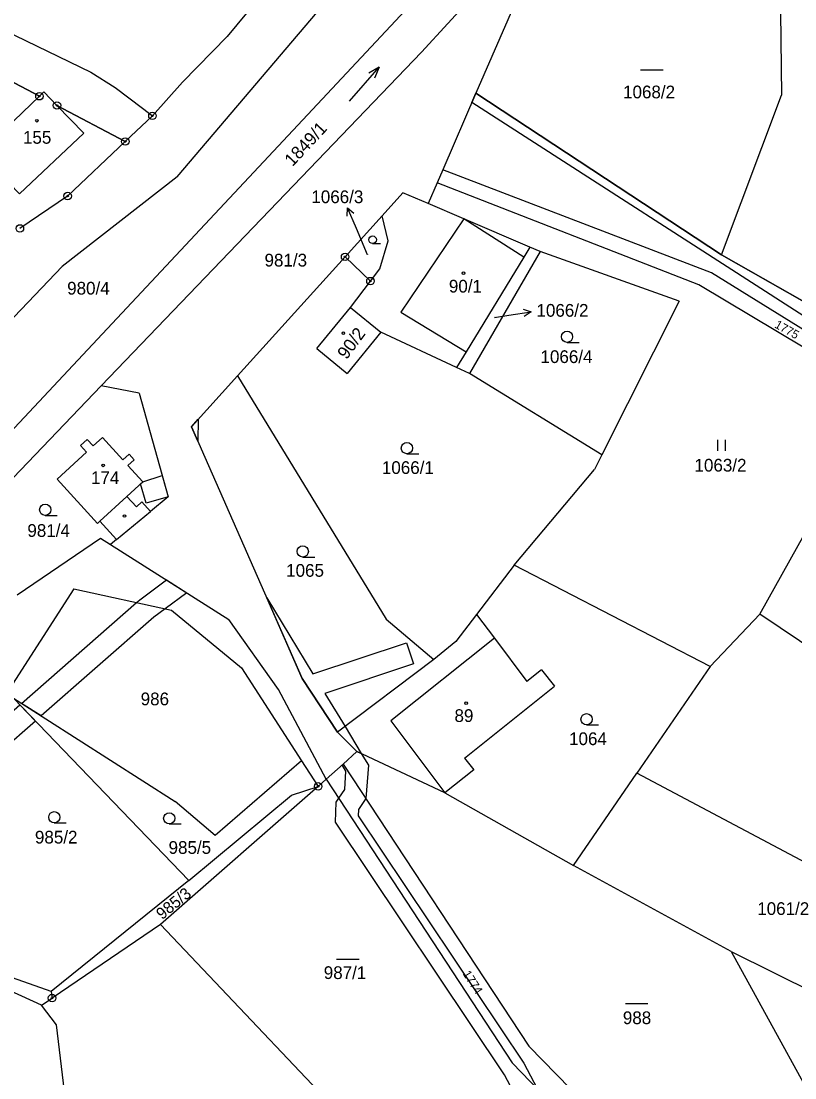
# Model space of a CAD drawing. Extents: x -546762 to -540209, y -1046851 to -1035694.
# Drawn here: x -543695 to -543591.5, y -1041824.4 to -1041683.1 of the extents above; entities that cross this region are included whole.
import ezdxf

# ---------------------------------------------------------------- set-up
doc = ezdxf.new("R2010")
doc.units = 0
for name, color, linetype in [('Vrstva 1', 7, 'Continuous'), ('Vrstva 16', 7, 'Continuous'), ('Vrstva 18', 7, 'Continuous'), ('Vrstva 19', 7, 'Continuous'), ('Vrstva 24', 7, 'Continuous'), ('Vrstva 25', 7, 'Continuous'), ('Vrstva 3', 7, 'Continuous'), ('Vrstva 30', 7, 'Continuous'), ('Vrstva 37', 7, 'Continuous'), ('Vrstva 4', 7, 'Continuous')]:
    doc.layers.add(name, color=color, linetype=linetype)

msp = doc.modelspace()

# ---------------------------------------------------------------- linework, layer by layer
at = {"layer": 'Vrstva 1'}
for p, q in [((-543658.84, -1041786.63), (-543655.29, -1041785.44)), ((-543672.56, -1041798.03), (-543658.84, -1041786.63)), ((-543672.56, -1041798.03), (-543690.99, -1041812.85)), ((-543676.36, -1041803.9), (-543690.87, -1041813.74)), ((-543690.99, -1041812.85), (-543690.87, -1041813.74)), ((-543692.27, -1041814.69), (-543690.87, -1041813.74))]:
    msp.add_line(p, q, dxfattribs=at)
for points in [[(-543593.64, -1041667.16), (-543593.33, -1041693.04)], [(-543641.49, -1041687.28), (-543627.37, -1041671.93)], [(-543658.62, -1041674.52), (-543667.47, -1041685.2), (-543673.41, -1041691.3), (-543677.45, -1041695.81)], [(-543674.15, -1041703.97), (-543649.79, -1041675.31)], [(-543626.72, -1041675.58), (-543634.2, -1041692.8)], [(-543720.78, -1041764.01), (-543643, -1041681.02)], [(-543706.63, -1041685.77), (-543692.56, -1041693.19)], [(-543641.49, -1041687.28), (-543684.31, -1041731.91)], [(-543692.56, -1041693.19), (-543691.96, -1041692.62), (-543690.21, -1041694.42)], [(-543634.2, -1041692.8), (-543638.64, -1041703.04)], [(-543601.37, -1041714.39), (-543634.2, -1041692.8)], [(-543601.37, -1041714.39), (-543593.33, -1041693.04)], [(-543690.21, -1041694.42), (-543686.63, -1041698.12), (-543695.23, -1041706.25), (-543700.53, -1041700.78), (-543692.56, -1041693.19)], [(-543690.21, -1041694.42), (-543681.08, -1041699.24)], [(-543681.08, -1041699.24), (-543677.45, -1041695.81)], [(-543681.08, -1041699.24), (-543688.79, -1041706.53), (-543695.17, -1041710.86)], [(-543674.15, -1041703.97), (-543689.53, -1041715.93)], [(-543638.64, -1041703.04), (-543639.38, -1041704.75)], [(-543602.7, -1041716.81), (-543638.64, -1041703.04)], [(-543639.38, -1041704.75), (-543640.6, -1041707.54)], [(-543604.41, -1041718.39), (-543639.38, -1041704.75)], [(-543646.74, -1041709.16), (-543643.97, -1041706.1)], [(-543640.6, -1041707.54), (-543643.97, -1041706.1)], [(-543635.79, -1041709.59), (-543640.6, -1041707.54)], [(-543646.74, -1041709.16), (-543651.69, -1041714.65)], [(-543645.91, -1041712.53), (-543646.74, -1041709.16)], [(-543626.97, -1041713.36), (-543635.79, -1041709.59)], [(-543647.06, -1041716.27), (-543645.91, -1041712.53)], [(-543625.6, -1041713.94), (-543635.04, -1041730.25)], [(-543626.97, -1041713.36), (-543627.8, -1041714.72)], [(-543625.6, -1041713.94), (-543626.97, -1041713.36)], [(-543607.02, -1041720.58), (-543625.6, -1041713.94)], [(-543651.69, -1041714.65), (-543666.07, -1041730.55)], [(-543651.69, -1041714.65), (-543648.3, -1041717.9)], [(-543627.8, -1041714.72), (-543635.51, -1041727.36)], [(-543579.06, -1041727.05), (-543601.37, -1041714.39)], [(-543689.53, -1041715.93), (-543716.11, -1041743.8)], [(-543648.3, -1041717.9), (-543647.06, -1041716.27)], [(-543579.17, -1041731.38), (-543602.7, -1041716.81)], [(-543650.98, -1041721.41), (-543648.3, -1041717.9)], [(-543583.37, -1041730.98), (-543604.41, -1041718.39)], [(-543607.02, -1041720.58), (-543617.34, -1041741.14)], [(-543655.46, -1041726.92), (-543650.98, -1041721.41)], [(-543650.98, -1041721.41), (-543646.91, -1041724.72)], [(-543646.91, -1041724.72), (-543651.39, -1041730.23)], [(-543636.78, -1041729.44), (-543646.91, -1041724.72)], [(-543655.46, -1041726.92), (-543651.39, -1041730.23)], [(-543635.51, -1041727.36), (-543636.78, -1041729.44)], [(-543635.04, -1041730.25), (-543636.78, -1041729.44)], [(-543666.07, -1041730.55), (-543672.23, -1041737.37)], [(-543666.07, -1041730.55), (-543646.18, -1041763.1)], [(-543617.34, -1041741.14), (-543635.04, -1041730.25)], [(-543684.31, -1041731.91), (-543698.08, -1041746.26)], [(-543679.24, -1041732.88), (-543684.31, -1041731.91)], [(-543679.24, -1041732.88), (-543675.36, -1041746.73)], [(-543596.22, -1041762.41), (-543580.22, -1041733.75)], [(-543672.23, -1041737.37), (-543657.42, -1041771.01)], [(-543686.19, -1041739.06), (-543687.08, -1041739.87)], [(-543686.19, -1041739.06), (-543685.38, -1041739.94)], [(-543684.13, -1041738.79), (-543685.38, -1041739.94)], [(-543681.39, -1041741.79), (-543684.13, -1041738.79)], [(-543686.27, -1041740.75), (-543690.19, -1041744.36)], [(-543687.08, -1041739.87), (-543686.27, -1041740.75)], [(-543680.58, -1041741.05), (-543681.39, -1041741.79)], [(-543679.9, -1041741.79), (-543680.58, -1041741.05)], [(-543680.72, -1041742.53), (-543679.9, -1041741.79)], [(-543617.34, -1041741.14), (-543618.32, -1041743.09)], [(-543678.73, -1041744.71), (-543680.72, -1041742.53)], [(-543629.09, -1041755.89), (-543618.32, -1041743.09)], [(-543690.19, -1041744.36), (-543684.79, -1041750.28)], [(-543680.89, -1041746.69), (-543678.73, -1041744.71)], [(-543680.89, -1041746.69), (-543679.6, -1041748.09)], [(-543675.36, -1041746.73), (-543677.7, -1041748.68)], [(-543678.87, -1041747.42), (-543679.6, -1041748.09)], [(-543677.7, -1041748.68), (-543678.87, -1041747.42)], [(-543682.24, -1041752.46), (-543677.7, -1041748.68)], [(-543684.79, -1041750.28), (-543684.5, -1041750.01)], [(-543684.5, -1041750.01), (-543682.24, -1041752.46)], [(-543695.54, -1041759.82), (-543684.39, -1041752.27)], [(-543684.39, -1041752.27), (-543683.04, -1041753.12)], [(-543682.24, -1041752.46), (-543683.04, -1041753.12)], [(-543683.04, -1041753.12), (-543667.22, -1041763.13)], [(-543629.09, -1041755.89), (-543634.11, -1041762.45)], [(-543602.89, -1041769.4), (-543629.09, -1041755.89)], [(-543687.98, -1041759.05), (-543696.98, -1041773.04)], [(-543687.98, -1041759.05), (-543674.92, -1041761.88)], [(-543674.92, -1041761.88), (-543665.56, -1041769.59)], [(-543660.58, -1041772.47), (-543667.22, -1041763.13)], [(-543646.18, -1041763.1), (-543639.82, -1041768.48)], [(-543634.11, -1041762.45), (-543636.89, -1041766.08)], [(-543634.11, -1041762.45), (-543631.72, -1041765.63)], [(-543602.89, -1041769.4), (-543596.22, -1041762.41)], [(-543577.6, -1041774.95), (-543596.22, -1041762.41)], [(-543636.89, -1041766.08), (-543639.82, -1041768.48)], [(-543631.72, -1041765.63), (-543627.37, -1041771.43)], [(-543639.82, -1041768.48), (-543652.71, -1041778.21)], [(-543665.56, -1041769.59), (-543657.51, -1041782.01)], [(-543625.42, -1041769.87), (-543627.37, -1041771.43)], [(-543625.42, -1041769.87), (-543623.67, -1041772.06)], [(-543602.89, -1041769.4), (-543612.68, -1041783.66)], [(-543657.42, -1041771.01), (-543652.71, -1041778.21)], [(-543635.71, -1041781.67), (-543623.67, -1041772.06)], [(-543654.2, -1041784.48), (-543660.58, -1041772.47)], [(-543696.04, -1041773.64), (-543674.43, -1041787.46)], [(-543696.04, -1041773.64), (-543672.56, -1041798.03)], [(-543652.71, -1041778.21), (-543650.11, -1041780.77)], [(-543657.51, -1041782.01), (-543669.07, -1041792.02)], [(-543657.51, -1041782.01), (-543655.29, -1041785.44)], [(-543650.11, -1041780.77), (-543651.96, -1041782.45)], [(-543638.36, -1041786.3), (-543650.11, -1041780.77)], [(-543635.71, -1041781.67), (-543634.47, -1041783.24)], [(-543651.96, -1041782.45), (-543654.2, -1041784.48)], [(-543651.96, -1041782.45), (-543627.14, -1041820.18)], [(-543634.47, -1041783.24), (-543638.36, -1041786.3)], [(-543654.2, -1041784.48), (-543655.29, -1041785.44)], [(-543654.2, -1041784.48), (-543629.36, -1041822.39)], [(-543621.17, -1041796.03), (-543612.68, -1041783.66)], [(-543555.05, -1041814.24), (-543612.68, -1041783.66)], [(-543655.29, -1041785.44), (-543676.36, -1041803.9)], [(-543638.36, -1041786.3), (-543621.17, -1041796.03)], [(-543669.07, -1041792.02), (-543674.43, -1041787.46)], [(-543600.05, -1041807.52), (-543621.17, -1041796.03)], [(-543646.37, -1041835.52), (-543676.36, -1041803.9)], [(-543690.99, -1041812.85), (-543714.27, -1041804.68)], [(-543692.27, -1041814.69), (-543714.27, -1041804.68)], [(-543600.05, -1041807.52), (-543560.44, -1041827.16)], [(-543600.05, -1041807.52), (-543584.78, -1041835.32)], [(-543690.28, -1041817.33), (-543692.27, -1041814.69)], [(-543686.39, -1041849.61), (-543690.28, -1041817.33)], [(-543627.14, -1041820.18), (-543614.13, -1041833.46)], [(-543629.36, -1041822.39), (-543624.43, -1041827.46)]]:
    msp.add_lwpolyline(points, dxfattribs=at)
at = {"layer": 'Vrstva 16'}
for p, q in [((-543650.18, -1041710.86), (-543651.36, -1041708.1)), ((-543629.79, -1041722.46), (-543626.82, -1041722.01))]:
    msp.add_line(p, q, dxfattribs=at)
for points in [[(-543651.42, -1041709.22), (-543651.36, -1041708.1), (-543650.5, -1041708.82)], [(-543648.67, -1041714.41), (-543650.18, -1041710.86)], [(-543631.69, -1041722.75), (-543629.79, -1041722.46)], [(-543627.89, -1041721.67), (-543626.82, -1041722.01), (-543627.74, -1041722.65)]]:
    msp.add_lwpolyline(points, dxfattribs=at)
at = {"layer": 'Vrstva 24'}
for centre, radius in [((-543692.56, -1041693.19), 0.5), ((-543692.56, -1041693.19), 0.1), ((-543690.21, -1041694.42), 0.5), ((-543690.21, -1041694.42), 0.1), ((-543677.45, -1041695.81), 0.5), ((-543677.45, -1041695.81), 0.1), ((-543681.08, -1041699.24), 0.5), ((-543681.08, -1041699.24), 0.1), ((-543688.79, -1041706.53), 0.5), ((-543688.79, -1041706.53), 0.1), ((-543695.17, -1041710.86), 0.5), ((-543651.69, -1041714.65), 0.5), ((-543651.69, -1041714.65), 0.1), ((-543648.3, -1041717.9), 0.5), ((-543648.3, -1041717.9), 0.1), ((-543655.29, -1041785.44), 0.5), ((-543655.29, -1041785.44), 0.1), ((-543690.87, -1041813.74), 0.5), ((-543690.87, -1041813.74), 0.1)]:
    msp.add_circle(centre, radius, dxfattribs=at)
at = {"layer": 'Vrstva 25'}
for p, q in [((-543612.17, -1041689.68), (-543609.17, -1041689.68)), ((-543648.01, -1041712.87), (-543646.94, -1041712.87)), ((-543622.01, -1041726.09), (-543620.41, -1041726.09)), ((-543601.84, -1041740.6), (-543601.84, -1041739.1)), ((-543600.84, -1041740.6), (-543600.84, -1041739.1)), ((-543643.43, -1041740.98), (-543641.83, -1041740.98)), ((-543691.79, -1041749.21), (-543690.19, -1041749.21)), ((-543657.35, -1041754.78), (-543655.75, -1041754.78)), ((-543619.4, -1041777.22), (-543617.8, -1041777.22)), ((-543690.57, -1041790.32), (-543688.97, -1041790.32)), ((-543675.2, -1041790.46), (-543673.6, -1041790.46)), ((-543652.82, -1041808.55), (-543649.82, -1041808.55)), ((-543614.21, -1041814.46), (-543611.21, -1041814.46))]:
    msp.add_line(p, q, dxfattribs=at)
for points in [[(-543651.09, -1041693.83), (-543647.13, -1041689.31), (-543648.5, -1041690.11)], [(-543647.13, -1041689.31), (-543647.75, -1041690.77)]]:
    msp.add_lwpolyline(points, dxfattribs=at)
for centre, radius in [((-543692.89, -1041696.46), 0.175), ((-543648.01, -1041712.37), 0.503), ((-543635.86, -1041716.83), 0.175), ((-543651.92, -1041724.86), 0.175), ((-543622.01, -1041725.34), 0.75), ((-543643.43, -1041740.23), 0.75), ((-543684.03, -1041742.53), 0.175), ((-543691.79, -1041748.46), 0.75), ((-543681.19, -1041749.3), 0.175), ((-543657.35, -1041754.03), 0.75), ((-543635.5, -1041774.31), 0.175), ((-543619.4, -1041776.47), 0.75), ((-543690.57, -1041789.57), 0.75), ((-543675.2, -1041789.71), 0.75)]:
    msp.add_circle(centre, radius, dxfattribs=at)
at = {"layer": 'Vrstva 3'}
for points in [[(-543692.56, -1041693.19), (-543691.96, -1041692.62), (-543690.21, -1041694.42)], [(-543690.21, -1041694.42), (-543686.63, -1041698.12), (-543695.23, -1041706.25), (-543700.53, -1041700.78), (-543692.56, -1041693.19)], [(-543635.79, -1041709.59), (-543644.22, -1041722.05)], [(-543627.8, -1041714.72), (-543635.79, -1041709.59)], [(-543627.8, -1041714.72), (-543635.51, -1041727.36)], [(-543655.46, -1041726.92), (-543650.98, -1041721.41)], [(-543650.98, -1041721.41), (-543646.91, -1041724.72)], [(-543644.22, -1041722.05), (-543635.51, -1041727.36)], [(-543646.91, -1041724.72), (-543651.39, -1041730.23)], [(-543655.46, -1041726.92), (-543651.39, -1041730.23)], [(-543686.19, -1041739.06), (-543687.08, -1041739.87)], [(-543686.19, -1041739.06), (-543685.38, -1041739.94)], [(-543684.13, -1041738.79), (-543685.38, -1041739.94)], [(-543681.39, -1041741.79), (-543684.13, -1041738.79)], [(-543686.27, -1041740.75), (-543690.19, -1041744.36)], [(-543687.08, -1041739.87), (-543686.27, -1041740.75)], [(-543680.58, -1041741.05), (-543681.39, -1041741.79)], [(-543679.9, -1041741.79), (-543680.58, -1041741.05)], [(-543680.72, -1041742.53), (-543679.9, -1041741.79)], [(-543678.73, -1041744.71), (-543680.72, -1041742.53)], [(-543690.19, -1041744.36), (-543684.79, -1041750.28)], [(-543680.89, -1041746.69), (-543678.73, -1041744.71)], [(-543680.89, -1041746.69), (-543684.5, -1041750.01)], [(-543684.79, -1041750.28), (-543684.5, -1041750.01)], [(-543631.72, -1041765.63), (-543645.57, -1041776.69)], [(-543631.72, -1041765.63), (-543627.37, -1041771.43)], [(-543625.42, -1041769.87), (-543627.37, -1041771.43)], [(-543625.42, -1041769.87), (-543623.67, -1041772.06)], [(-543635.71, -1041781.67), (-543623.67, -1041772.06)], [(-543645.57, -1041776.69), (-543638.36, -1041786.3)], [(-543635.71, -1041781.67), (-543634.47, -1041783.24)], [(-543634.47, -1041783.24), (-543638.36, -1041786.3)]]:
    msp.add_lwpolyline(points, dxfattribs=at)
at = {"layer": 'Vrstva 30'}
for p, q in [((-543634.73, -1041694.01), (-543634.2, -1041692.8)), ((-543634.2, -1041692.8), (-543601.37, -1041714.39)), ((-543567.29, -1041737.46), (-543634.73, -1041694.01)), ((-543601.37, -1041714.39), (-543579.06, -1041727.05))]:
    msp.add_line(p, q, dxfattribs=at)
for points in [[(-543711.17, -1041684.4), (-543702.42, -1041684.93), (-543697.27, -1041684.36), (-543685.67, -1041689.96), (-543682.42, -1041692.02), (-543678.79, -1041694.79), (-543677.45, -1041695.81), (-543681.08, -1041699.24), (-543690.21, -1041694.42), (-543691.96, -1041692.62), (-543692.56, -1041693.19), (-543706.63, -1041685.77), (-543711.24, -1041685.68), (-543711.17, -1041684.4)], [(-543672.23, -1041737.37), (-543671.32, -1041736.36), (-543671.39, -1041739.29), (-543672.23, -1041737.37)], [(-543678.73, -1041744.71), (-543676.15, -1041743.9), (-543675.36, -1041746.73), (-543678.28, -1041747.57), (-543679.04, -1041745), (-543678.73, -1041744.71)], [(-543679.58, -1041760.87), (-543679.14, -1041760.49), (-543675.58, -1041757.84), (-543672.86, -1041759.56), (-543675.74, -1041761.7), (-543677.26, -1041762.83), (-543692.31, -1041776.02), (-543694.94, -1041774.34), (-543679.58, -1041760.87)], [(-543642.53, -1041769.08), (-543654.38, -1041773.03), (-543651.7, -1041777.45), (-543649.52, -1041781.05), (-543650.11, -1041780.77), (-543652.71, -1041778.21), (-543657.42, -1041771.01), (-543662.17, -1041760.22), (-543655.98, -1041770.4), (-543643.48, -1041766.23), (-543642.53, -1041769.08)], [(-543702.47, -1041784.93), (-543709.63, -1041786.58), (-543716.02, -1041779.5), (-543714.03, -1041777.23), (-543708.67, -1041783.17), (-543707.35, -1041783.38), (-543703.87, -1041782.17), (-543695.17, -1041774.54), (-543693.09, -1041776.71), (-543702.47, -1041784.93)], [(-543651.61, -1041783.39), (-543652.1, -1041782.58), (-543651.96, -1041782.45), (-543650.11, -1041780.77), (-543649.52, -1041781.05), (-543648.57, -1041782.61), (-543648.91, -1041787.08), (-543649.91, -1041788.52), (-543649.93, -1041789.36), (-543627.79, -1041822.44), (-543626, -1041825.84), (-543625.04, -1041827.68), (-543624.38, -1041828.93), (-543625.53, -1041832.86), (-543628.41, -1041832.02), (-543627.6, -1041829.25), (-543627.88, -1041828.73), (-543630.37, -1041823.98), (-543652.95, -1041790.24), (-543652.89, -1041787.54), (-543652.53, -1041787.03), (-543651.72, -1041785.86), (-543651.61, -1041783.39)]]:
    msp.add_lwpolyline(points, dxfattribs=at)
at = {"layer": 'Vrstva 37'}
for centre in [(-543692.89, -1041696.46), (-543635.86, -1041716.83), (-543651.92, -1041724.86), (-543684.03, -1041742.53), (-543635.5, -1041774.31)]:
    msp.add_circle(centre, 0.175, dxfattribs=at)
at = {"layer": 'Vrstva 4'}
for points in [[(-543635.79, -1041709.59), (-543644.22, -1041722.05)], [(-543627.8, -1041714.72), (-543635.79, -1041709.59)], [(-543644.22, -1041722.05), (-543635.51, -1041727.36)], [(-543680.89, -1041746.69), (-543684.5, -1041750.01)], [(-543631.72, -1041765.63), (-543645.57, -1041776.69)], [(-543645.57, -1041776.69), (-543638.36, -1041786.3)]]:
    msp.add_lwpolyline(points, dxfattribs=at)

# ---------------------------------------------------------------- texts
at = {"layer": 'Vrstva 16'}
for s, p in [('1066/3', (-543656.2, -1041707.48)), ('1066/2', (-543626.1, -1041722.66))]:
    msp.add_text(s, height=1.7, dxfattribs=at).set_placement(p)
at = {"layer": 'Vrstva 18'}
for s, height, p in [('1068/2', 1.7, (-543614.52, -1041693.47)), ('981/3', 1.7, (-543662.46, -1041715.95)), ('1066/3', 0.1, (-543648.89, -1041714.41)), ('980/4', 1.7, (-543688.85, -1041719.7)), ('1066/2', 0.1, (-543631.91, -1041722.75)), ('1066/4', 1.7, (-543625.56, -1041728.85)), ('1066/1', 1.7, (-543646.77, -1041743.68)), ('1063/2', 1.7, (-543604.97, -1041743.36)), ('981/4', 1.7, (-543694.17, -1041752.09)), ('1065', 1.7, (-543659.57, -1041757.42)), ('986', 1.7, (-543679.02, -1041774.6)), ('1064', 1.7, (-543621.74, -1041779.92)), ('985/2', 1.7, (-543693.16, -1041793.08)), ('985/5', 1.7, (-543675.29, -1041794.46)), ('1061/2', 1.7, (-543596.58, -1041802.63)), ('987/1', 1.7, (-543654.54, -1041811.19)), ('988', 1.7, (-543614.55, -1041817.22))]:
    msp.add_text(s, height=height, dxfattribs=at).set_placement(p)
for s, height, rotation, p in [('1849/1', 1.7, 46.9428, (-543658.72, -1041702.67)), ('1775', 1.14, 330.8365, (-543594.36, -1041724.05)), ('985/3', 1.56, 39.1472, (-543676.16, -1041803.33)), ('1774', 1.14, 302.682, (-543636, -1041810.49))]:
    msp.add_text(s, height=height, rotation=rotation, dxfattribs=at).set_placement(p)
at = {"layer": 'Vrstva 19'}
for s, p in [('155', (-543694.76, -1041699.54)), ('90/1', (-543637.81, -1041719.43)), ('174', (-543685.67, -1041745.04)), ('89', (-543637.06, -1041776.83))]:
    msp.add_text(s, height=1.7, dxfattribs=at).set_placement(p)
msp.add_text('90/2', height=1.7, rotation=53.4542, dxfattribs=at).set_placement((-543651.5, -1041728.48))

doc.saveas('drawing.dxf')
